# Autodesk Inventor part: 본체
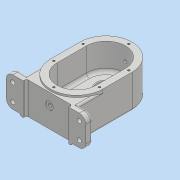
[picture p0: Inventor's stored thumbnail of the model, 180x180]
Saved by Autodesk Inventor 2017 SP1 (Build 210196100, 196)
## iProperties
Part Number: 본체
Material: 일반
Document SubType Name: Modeling
Designer: MRC
Density: 1 g/cm^3
Appearance: 기본값
Author: MRC
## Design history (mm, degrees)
sketch "스케치1"
  geometry: L1 (-40, 66)-(40, 66); L2 (40, 66)-(40, -66); L3 (40, -66)-(-40, -66); L4 (-40, -66)-(-40, 66); 3 further points
  constraints: 8 end point, 2 midpoint, 2 parallel, 1 horizontal, 1 horizontal alignment, 1 perpendicular, 1 vertical alignment
  dimensions: "d0" = 80 distance of L1.start L1.end; "d1" = 132 distance of L1.end L2.end
extrude "돌출1" new body sketch "스케치1" stored distance "d2" = 49; taper "d3" = 0 deg
fillet "모깎기1" dims "d4" = 40
sketch "스케치2"
  geometry: L1 (-40, -66)-(40, -66) reference; L2 (-61, -66)-(61, -66); L3 (61, -66)-(61, -56); L4 (61, -56)-(-61, -56); L5 (-61, -56)-(-61, -66); 3 further points
  constraints: 8 end point, 3 midpoint, 2 parallel, 1 horizontal, 1 perpendicular, 1 vertical alignment
  dimensions: "d5" = 10 distance between parallel lines of L1 L4; "d6" = 122 distance between parallel lines of L3 L5
extrude "돌출2" join sketch "스케치2" distance "d7" = 46; taper "d8" = 0 deg
sketch "스케치3"
  geometry: L1 (0, 56)-(0, -49); L2 (-30, 26)-(-30, -19); L3 (30, -19)-(30, 26); A1 r 40 centre (0, 26) between (40, 26) and (-40, 26) reference; A2 r 30 centre (0, 26) between (30, 26) and (-30, 26); A3 r 30 centre (0, -19) between (-30, -19) and (30, -19); 2 further points
  constraints: 8 end point, 6 point on circle, 4 tangent, 2 centre point, 2 point on line, 1 coincident, 1 midpoint, 1 parallel, 1 vertical
  dimensions: "d10" = 60 distance between parallel lines of L3 L2; "d11" = 45 distance of A3.centre A2.centre
extrude "돌출3" cut sketch "스케치3" distance "d12" = 38; taper "d13" = 0 deg
sketch "스케치4"
  geometry: L1 (-30, -19)-(-30, 26) reference; L2 (30, 26)-(30, -19) reference; L3 (40, -56)-(40, 26) reference; L4 (-40, 26)-(-40, -56) reference; L5 (0, 66)-(0, -59); L6 (-40, 26)-(-40, -19); L7 (40, -19)-(40, 26); A1 r 30 centre (0, -19) between (-30, -19) and (30, -19) reference; A2 r 30 centre (0, 26) between (30, 26) and (-30, 26) reference; A3 r 40 centre (0, 26) between (40, 26) and (-40, 26) reference; A4 r 40 centre (0, 26) between (40, 26) and (-40, 26); A5 r 40 centre (0, -19) between (-40, -19) and (40, -19); 2 further points
  constraints: 8 end point, 6 point on circle, 4 tangent, 2 centre point, 2 point on line, 1 coincident, 1 midpoint, 1 parallel, 1 vertical
  dimensions: "d14" = 80 distance between parallel lines of L7 L6; "d15" = 45 distance of A5.centre A2.centre
extrude "돌출4" join sketch "스케치4" distance "d16" = 3; taper "d17" = 0 deg
sketch "스케치7"
  geometry: L1 (-40, -66)-(40, -66) reference; L2 (0, 52)-(0, -45); L3 (-26, 26)-(-26, -19); L4 (26, -19)-(26, 26); L5 (-26, -4)-(26, -4); A1 r 40 centre (0, 26) between (40, 26) and (-40, 26) reference; A2 r 26 centre (0, 26) between (26, 26) and (-26, 26); A3 r 26 centre (0, -19) between (-26, -19) and (26, -19); 3 further points
  constraints: 10 end point, 6 point on circle, 4 tangent, 3 point on line, 2 centre point, 2 midpoint, 1 coincident, 1 horizontal, 1 parallel, 1 perpendicular, 1 vertical, 1 vertical alignment
  dimensions: "d24" = 52 distance between parallel lines of L4 L3; "d25" = 30 distance from line of L5 A1.centre; "d26" = 47 distance from line of L1 A3.centre
extrude "돌출6" join sketch "스케치7" distance "d27" = 11; taper "d28" = 0 deg
sketch "스케치9"
  geometry: L1 (-26, 26)-(-26, -19) reference; L2 (26, -19)-(26, 26) reference; L3 (-26, -4)-(26, -4) reference; L4 (-26, -4)-(26, -4); L5 (-26, -19)-(-26, 26) reference; L6 (-26, -4)-(-26, 26); L7 (26, -4)-(26, 26); A1 r 26 centre (0, 26) between (26, 26) and (-26, 26); 1 further point
  constraints: 6 end point, 3 collinear, 2 point on circle, 2 tangent, 1 centre point
extrude "돌출7" cut sketch "스케치9" distance "d29" = 3; taper "d30" = 0 deg
sketch "스케치11"
  geometry: C1 r 14 at (0, 26); A1 r 30 centre (0, 26) between (30, 26) and (-30, 26) reference; 1 further point
  constraints: 1 centre point, 1 coincident
  dimensions: "d32" = 28 diameter of C1
extrude "돌출8" cut sketch "스케치11" distance "d33" = 8; taper "d34" = 0 deg
sketch "스케치13"
  geometry: C1 r 14 at (0, 26); A1 r 26 centre (0, 26) between (26, 26) and (-26, 26) reference; 1 further point
  constraints: 1 centre point, 1 coincident
  dimensions: "d35" = 28 diameter of C1
extrude "돌출9" cut sketch "스케치13" distance "d36" = 4; taper "d37" = 0 deg
sketch "스케치14"
  geometry: C1 r 14 at (0, 0) reference; C2 r 11 at (0, 0); 1 further point
  constraints: 1 centre point, 1 coincident
  dimensions: "d38" = 22 diameter of C2
extrude "돌출10" cut sketch "스케치14" stored distance "d39" = 4; taper "d40" = 0 deg
sketch "스케치15"
  geometry: C1 r 14 at (0, -19); A1 r 30 centre (0, -19) between (-30, -19) and (30, -19) reference; 1 further point
  constraints: 1 centre point, 1 coincident
  dimensions: "d41" = 28 diameter of C1
extrude "돌출11" cut sketch "스케치15" distance "d42" = 8; taper "d43" = 0 deg
sketch "스케치16"
  geometry: C1 r 14 at (0, 0) reference; C2 r 10 at (0, 0); 1 further point
  constraints: 1 centre point, 1 coincident
  dimensions: "d44" = 20 diameter of C2
extrude "돌출12" cut sketch "스케치16" distance "d45" = 4; taper "d46" = 0 deg
sketch "스케치17"
  geometry: L1 (-61, -66)-(61, -66) reference; L2 (-35, -61)-(35, -61); L3 (35, -61)-(35, -66); L4 (35, -66)-(-35, -66); L5 (-35, -66)-(-35, -61); 3 further points
  constraints: 8 end point, 3 midpoint, 2 parallel, 1 horizontal, 1 perpendicular, 1 vertical alignment
  dimensions: "d47" = 5 distance between parallel lines of L1 L2; "d48" = 70 distance between parallel lines of L3 L5
extrude "돌출13" cut sketch "스케치17" stored distance "d49" = 4; taper "d50" = 0 deg
sketch "스케치18"
  geometry: A1 r 30 centre (0, 26) between (30, 26) and (-30, 26) reference; A2 r 30 centre (0, -19) between (-30, -19) and (30, -19) reference; 3 further points
  constraints: 2 vertical alignment
  dimensions: "d51" = 35 distance of A1.centre point (0, 61); "d52" = 35 distance of point (0, -54) A2.centre
hole "구멍1" sketch "스케치18" at (0, 61), (0, -54) diameter "d53" = 3.242; stored, may be unused: countersink angle "d57" = 90 deg, drill point angle "d59" = 118 deg; dims "d54" = 8, "d55" = 4, "d56" = 2, "d58" = 10
sketch "스케치19"
  geometry: A1 r 30 centre (0, 26) between (30, 26) and (-30, 26) reference; A2 r 30 centre (0, -19) between (-30, -19) and (30, -19) reference; 5 further points
  constraints: 4 horizontal alignment
  dimensions: "d60" = 35 distance of A1.centre point (-35, 26); "d61" = 35 distance of point (35, 26) A1.centre; "d62" = 35 distance of A2.centre point (-35, -19); "d63" = 35 distance of point (35, -19) A2.centre
hole "구멍2" sketch "스케치19" at (-35, 26), (35, 26), (-35, -19), (35, -19) diameter "d64" = 3.242; stored, may be unused: countersink angle "d68" = 90 deg, drill point angle "d70" = 118 deg; dims "d65" = 8, "d66" = 4, "d67" = 2, "d69" = 10
node "작업 평면5"
sketch "스케치20"
  geometry: L1 (40, 27.5)-(-40, 27.5) reference; C1 r 6 at (0, 6.5); 1 further point
  constraints: 1 centre point, 1 vertical alignment
  dimensions: "d128" = 12 diameter of C1; "d129" = 21 distance from line of C1.centre L1
extrude "돌출14" join sketch "스케치20" stored distance "d73" = 4; taper "d74" = 0 deg
sketch "스케치21"
  geometry: L1 (75, 3)-(-5, 3) reference; 2 further points
  constraints: 1 vertical alignment
  dimensions: "d84" = 21 distance from line of point (35, -18) L1
hole "구멍4" sketch "스케치21" at (35, -18) diameter "d85" = 4.917; stored, may be unused: countersink angle "d89" = 90 deg, drill point angle "d91" = 118 deg; dims "d86" = 12, "d87" = 12, "d88" = 1, "d90" = 17.1
fillet "모깎기2" dims "d92" = 5
fillet "모깎기3" dims "d93" = 10
sketch "스케치23"
  geometry: A1 r 10 centre (11, 36) between (21, 36) and (11, 46) reference; A2 r 10 centre (11, 10) between (11, 0) and (21, 10) reference; 3 further points
  constraints: 2 coincident
hole "구멍5" sketch "스케치23" at (11, 10), (11, 36) diameter "d94" = 6.6; stored, may be unused: countersink angle "d98" = 90 deg, drill point angle "d100" = 118 deg; dims "d95" = 12, "d96" = 11, "d97" = 2, "d99" = 17.1
fillet "모깎기4" dims "d101" = 3
fillet "모깎기5" dims "d102" = 3
fillet "모깎기6" dims "d103" = 3
fillet "모깎기7" dims "d104" = 3
chamfer "모따기1" distance "d105" = 1; stored, may be unused: second distance "d106" = 2, angle "d107" = 45 deg
fillet "모깎기8" dims "d108" = 0.3
chamfer "모따기2" distance "d109" = 1; stored, may be unused: second distance "d110" = 2, angle "d111" = 45 deg
fillet "모깎기9" dims "d112" = 3
sketch "스케치24"
  geometry: A1 r 26 centre (0, 26) between (26, 26) and (-26, 26) reference; 2 further points
  constraints: 1 vertical alignment
  dimensions: "d114" = 20 distance of A1.centre point (0, 46)
hole "구멍6" sketch "스케치24" at (0, 46) diameter "d115" = 3.242; stored, may be unused: countersink angle "d119" = 90 deg, drill point angle "d121" = 118 deg; dims "d116" = 8, "d117" = 11, "d118" = 2, "d120" = 10
sketch "스케치25"
  geometry: L1 (-51, -66)-(-40, -66) reference; A1 r 37 centre (0, 26) between (37, 26) and (-37, 26) reference; 2 further points
  constraints: 1 vertical alignment, 1 other
  dimensions: "d125" = 12 distance from line of point (0, -54) L1
feature "엠보싱1" sketch "스케치25" dims "d126" = 0.5, "d127" = 0
fillet "모깎기11" dims "d130" = 3
hole "구멍7" diameter "d133" = 4.917; stored, may be unused: countersink angle "d137" = 90 deg, drill point angle "d139" = 118 deg; dims "d131" = 10, "d132" = 10, "d134" = 12, "d135" = 11, "d136" = 2, "d138" = 17.1
node "솔리드1"
mirror "미러1"
pattern_circular "원형 패턴1" dims angle "d123" = 360 deg
